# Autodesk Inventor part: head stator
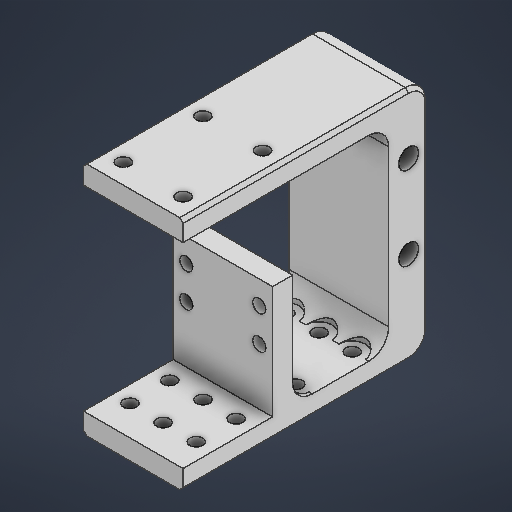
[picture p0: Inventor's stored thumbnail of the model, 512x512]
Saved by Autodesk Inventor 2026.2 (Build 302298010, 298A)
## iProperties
Created: 2026-04
Part Number: head stator
Material: 일반
Document SubType Name: Modeling
Designer: work
Density: 1 g/cm^3
Appearance: 기본값
Author: work
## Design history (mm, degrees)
sketch "스케치1"
  geometry: L1 (-12.5, 25)-(12.5, 25); L2 (12.5, 25)-(12.5, -25); L3 (12.5, -25)-(-12.5, -25); L4 (-12.5, -25)-(-12.5, 25); L5 (-12.5, 25)-(12.5, -25); L6 (12.5, 25)-(-12.5, -25); L7 (-24.5, 34)-(-0.5, 34); L8 (-0.5, 34)-(-0.5, 16); L9 (-0.5, 16)-(-24.5, 16); L10 (-24.5, 16)-(-24.5, 34); L11 (-24.5, 34)-(-0.5, 16); L12 (-0.5, 34)-(-24.5, 16); L13 (-18.5, -31)-(18.5, -31); L14 (18.5, -31)-(18.5, -19); L15 (18.5, -19)-(-18.5, -19); L16 (-18.5, -19)-(-18.5, -31); L17 (-18.5, -31)-(18.5, -19); L18 (18.5, -31)-(-18.5, -19); L19 (12.5, 25)-(24.5, 25); L20 (24.5, 43)-(30.5, 43); L21 (30.5, 43)-(30.5, -31); L22 (30.5, -31)-(24.5, -31); L23 (24.5, -31)-(24.5, 43); L24 (18.5, -19)-(24.5, -19); L25 (18.5, -31)-(24.5, -31); L26 (-18.5, 10)-(-24.5, 10); L27 (-24.5, 10)-(-24.5, -31); L28 (-24.5, -31)-(-18.5, -31); L29 (-18.5, -31)-(-18.5, 10); L30 (30.5, 37)-(24.5, 37); L31 (24.5, 37)-(24.5, 13); L32 (24.5, 13)-(30.5, 13); L33 (30.5, 13)-(30.5, 37); L34 (-6.5, 16)-(-18.5, 16); L35 (-18.5, 16)-(-18.5, 10); L36 (-18.5, 10)-(-6.5, 10); L37 (-6.5, 10)-(-6.5, 16); L38 (-0.5, 16)-(-24.5, 16); L39 (-24.5, 16)-(-24.5, 10); L40 (-24.5, 10)-(-0.5, 10); L41 (-0.5, 10)-(-0.5, 16); L42 (-18.5, -19)-(-34.5, -19); L43 (-34.5, -19)-(-34.5, -31); L44 (-34.5, -31)-(-18.5, -31); L45 (-18.5, -31)-(-18.5, -19); L46 (-34.5, -31)-(-40.5, -31); L47 (-40.5, -31)-(-40.5, 16); L48 (-40.5, 16)-(-34.5, 16); L49 (-34.5, 16)-(-34.5, -31); L50 (-34.5, 10)-(-24.5, 10); L51 (-24.5, 10)-(-24.5, 16); L52 (-24.5, 16)-(-34.5, 16); L53 (-34.5, 16)-(-34.5, 10); C1 r 4 at (12.5, 25); C2 r 3 at (12.5, -25); C3 r 3 at (-12.5, -25); 17 further points
  constraints: 106 end point, 23 parallel, 17 midpoint, 13 horizontal, 11 perpendicular, 5 point on line, 3 centre point, 3 coincident
  dimensions: "d0" = 25 distance of L2.end L3.end; "d1" = 50 distance of L1.end L2.end; "d2" = 8 diameter of C1; "d3" = 24 distance of L8.end L9.end; "d4" = 18 distance of L7.end L8.end; "d5" = 6 diameter of C2; "d6" = 6 diameter of C3; "d7" = 6 distance from line of L2.end L14; "d8" = 6 distance from line of L15 L2.end; "d9" = 12 distance of L19.end L19.start; "d11" = 24 distance from line of point (27.5, 13) L30; "d13" = 6 distance between parallel lines of L23 L21; "d14" = 6 distance between parallel lines of L30 L20; "d15" = 6 distance between parallel lines of L29 L27; "d17" = 6 distance of L34.end L35.end; "d18" = 12 distance from line of point (-18.5, 13) L37; "d19" = 6 distance between parallel lines of L39 L35; "d41" = 6 distance between parallel lines of L47 L49; "d42" = 10 distance between parallel lines of L53 L39
extrude "돌출1" new body sketch "스케치1" distance "d20" = 30; taper "d21" = 0 deg
sketch "스케치2"
  geometry: L1 (0, 74)-(0, 0) reference; L2 (0, 0)-(30, 0) reference; L3 (30, 74)-(30, 0) reference; L4 (0, 74)-(30, 74) reference; L5 (15, 0)-(15, 74); L6 (0, 37)-(30, 37); L7 (24, 30)-(6, 30); L8 (6, 30)-(6, 6); L9 (6, 6)-(24, 6); L10 (24, 6)-(24, 30); L11 (24, 30)-(6, 6); L12 (6, 30)-(24, 6); C1 r 2 at (6, 6); C2 r 2 at (24, 6); C3 r 2 at (24, 30); C4 r 2 at (6, 30); 2 further points
  constraints: 16 end point, 6 midpoint, 4 centre point, 4 coincident, 2 parallel, 1 horizontal, 1 perpendicular, 1 point on line
  dimensions: "d22" = 6 distance between parallel lines of L2 L9; "d23" = 24 distance of L7.end L8.end; "d24" = 18 distance of L8.end L9.end; "d25" = 4 diameter of C1; "d26" = 4 diameter of C2; "d27" = 4 diameter of C3; "d28" = 4 diameter of C4
extrude "돌출2" cut sketch "스케치2" stored distance "d29" = 36; taper "d30" = 0 deg
fillet "모깎기1" dims "d31" = 6
sketch "스케치4"
  geometry: L1 (30, 31)-(30, 25) reference; L2 (0, 31)-(0, 25) reference; L3 (0, 28)-(30, 28); L4 (26, 23)-(4, 23); L5 (4, 23)-(4, 33); L6 (4, 33)-(26, 33); L7 (26, 33)-(26, 23); L8 (26, 23)-(4, 33); L9 (4, 23)-(26, 33); C1 r 2 at (4, 23); C2 r 2 at (4, 33); C3 r 2 at (26, 33); C4 r 2 at (26, 23); 2 further points
  constraints: 14 end point, 5 midpoint, 4 centre point, 4 coincident, 2 parallel, 1 horizontal, 1 perpendicular
  dimensions: "d44" = 10 distance of L4.end L5.end; "d45" = 4 distance between parallel lines of L2 L5; "d46" = 4 diameter of C1; "d47" = 4 diameter of C2; "d48" = 4 diameter of C3; "d49" = 4 diameter of C4
extrude "돌출4" cut sketch "스케치4" distance "d50" = 30; taper "d51" = 0 deg
sketch "스케치5"
  geometry: L1 (16, -9.5)-(10, -9.5) reference; L2 (16, -0.5)-(16, -34.5) reference; L3 (10, -0.5)-(16, -0.5) reference; L4 (10, -28.5)-(10, -0.5) reference; L5 (-13, -34.5)-(4, -34.5) reference; L6 (-19, 18.5)-(-19, -28.5) reference; L7 (43, 24.5)-(-13, 24.5) reference; L8 (43, 30.5)-(43, 24.5) reference; L9 (-25, 30.5)-(43, 30.5) reference; L10 (-31, -34.5)-(-31, 24.5) reference; L11 (10, -40.5)-(-25, -40.5) reference; L12 (4, -34.5)-(43, -34.5); L13 (43, -34.5)-(43, -40.5); L14 (43, -40.5)-(4, -40.5); L15 (4, -40.5)-(4, -34.5); L16 (43, 30.5)-(43, 24.5) reference; C1 r 3 at (-25, 12.5) reference; C2 r 3 at (-25, -12.5) reference; A1 r 6 centre (10, -34.5) between (10, -40.5) and (16, -34.5) reference; A2 r 6 centre (4, -28.5) between (4, -34.5) and (10, -28.5) reference; A3 r 6 centre (-13, -28.5) between (-19, -28.5) and (-13, -34.5) reference; A4 r 6 centre (-13, 18.5) between (-13, 24.5) and (-19, 18.5) reference; A5 r 6 centre (-25, 24.5) between (-25, 30.5) and (-31, 24.5) reference; A6 r 6 centre (-25, -34.5) between (-31, -34.5) and (-25, -40.5) reference; 3 further points
  constraints: 8 end point, 2 parallel, 1 collinear, 1 horizontal, 1 perpendicular, 1 point on circle, 1 point on line
  dimensions: "d52" = 6 distance of L14.end L12.start
extrude "돌출5" join sketch "스케치5" stored distance "d53" = 10; taper "d54" = 0 deg
sketch "스케치6"
  geometry: L1 (0, 68)-(0, 0) reference; L2 (30, 0)-(0, 0) reference; L3 (30, 68)-(30, 0) reference; L4 (0, 68)-(30, 68) reference; L5 (25, 65)-(5, 65); L6 (5, 65)-(5, 5); L7 (5, 5)-(25, 5); L8 (25, 5)-(25, 65); L9 (0, 35)-(30, 35) reference; L10 (25, 65)-(5, 5); L11 (5, 65)-(25, 5); L12 (6, 35)-(2, 35) reference; L13 (6, 35)-(2, 35) reference; L14 (0, 35)-(0, 41) reference; L15 (0, 41)-(30, 41) reference; L16 (30, 35)-(30, 41) reference; L17 (0, 35)-(30, 35) reference; L18 (25, 47)-(5, 47); L19 (5, 47)-(5, 65); L20 (5, 65)-(25, 65); L21 (25, 65)-(25, 47); L22 (30, 6)-(0, 6) reference; L23 (25, 12)-(5, 12); L24 (5, 12)-(5, 29); L25 (5, 29)-(25, 29); L26 (25, 29)-(25, 12); L27 (25, 59)-(5, 59); L28 (15, 5)-(15, 65); 14 further points
  constraints: 32 end point, 9 midpoint, 9 point on line, 8 coincident, 6 parallel, 4 perpendicular, 3 horizontal
  dimensions: "d56" = 5 distance between parallel lines of L1 L6; "d57" = 5 distance between parallel lines of L2 L7; "d58" = 6 distance between parallel lines of L9 L25; "d59" = 6 distance between parallel lines of L22 L23; "d60" = 6 distance between parallel lines of L15 L18; "d61" = 6 distance between parallel lines of L5 L27
hole "구멍1" sketch "스케치6" at (25, 12), (25, 29), (25, 59), (25, 47), (5, 59), (5, 47), (5, 29), (5, 12), (15, 47), (15, 59), (15, 29), (15, 12) diameter "d62" = 4; stored, may be unused: countersink angle "d66" = 90 deg, drill point angle "d68" = 118 deg; dims "d63" = 6, "d64" = 6.2, "d65" = 3, "d67" = 6 (= d59)
chamfer "모따기1" distance "d69" = 1; stored, may be unused: second distance "d70" = 2, angle "d71" = 45 deg
sketch "스케치7"
  geometry: L1 (29, -39)-(29, 29) reference; L2 (1, -39)-(29, -39) reference; L3 (1, 29)-(1, -39) reference; L4 (29, 29)-(1, 29) reference; C1 r 2 at (15, 17) reference; C2 r 2 at (15, 0) reference; C3 r 2 at (15, -30) reference; C4 r 2 at (15, -18) reference; C5 r 2 at (5, 17) reference; C6 r 2 at (5, 0) reference; C7 r 2 at (5, -18) reference; C8 r 2 at (5, -30) reference; C9 r 2 at (25, -18) reference; C10 r 2 at (25, -30) reference; C11 r 2 at (25, 0) reference; C12 r 2 at (25, 17) reference; C13 r 4 at (25, 17); C14 r 4 at (25, 0); C15 r 4 at (15, 0); C16 r 4 at (15, 17); C17 r 4 at (5, 17); C18 r 4 at (5, 0); 1 further point
  constraints: 6 centre point, 1 coincident
  dimensions: "d72" = 8 diameter of C13; "d73" = 8 diameter of C14; "d74" = 8 diameter of C15; "d75" = 8 diameter of C16; "d76" = 8 diameter of C17; "d77" = 8 diameter of C18
extrude "돌출6" cut sketch "스케치7" distance "d78" = 10; taper "d79" = 0 deg
feature "д耀ж耀и耀к耀м耀о耀р耀т耀" dims "d0" = 25, "d1" = 50, "d2" = 8, "d3" = 24, "d4" = 18, "d5" = 6, "d6" = 6, "d7" = 6, "d8" = 6, "d9" = 12, "d11" = 24, "d13" = 6, "d14" = 6, "d15" = 6, "d17" = 6, "d18" = 12, "d19" = 6, "d20" = 30, "d21" = 0, "d22" = 6, "d23" = 24, "d24" = 18, "d25" = 4, "d26" = 4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
node "솔리드1"
node "투영된 루프1"
node "투영된 루프3"
node "투영된 루프4"
node "투영된 루프5"
node "투영된 루프6"
node "투영된 루프7"
feature "A9D066F2-1C7D-4E18-AEED-F7BC21143FA4" dims "d62" = 4, "d63" = 6, "d64" = 6.2, "d65" = 3, "d66" = 90 deg, "d67" = 6 (= d59), "d68" = 118 deg
